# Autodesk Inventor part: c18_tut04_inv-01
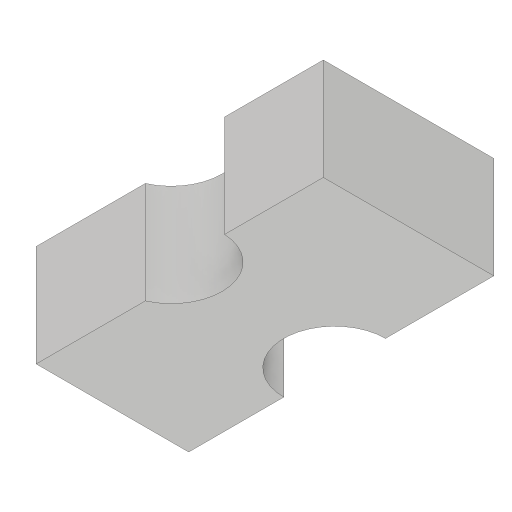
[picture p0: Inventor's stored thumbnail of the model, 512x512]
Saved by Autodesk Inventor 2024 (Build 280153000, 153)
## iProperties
Created: 2017-06
Part Number: c18_tut04_inv-01
Material: Generic
Document SubType Name: Modeling
Designer: CADCIM 00
Density: 1 g/cm^3
Appearance: Default
Author: CADCIM 00
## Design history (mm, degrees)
derived "c18_tut04_inv.ipt"
feature "Solid1::c18_tut04_inv.ipt"
tag "TaggingFeature1"
body "Solid1"
other parameters: "d2" = 10, "d4" = 0, "d5" = 6, "RAD" = 10, "FILLET" = 6
